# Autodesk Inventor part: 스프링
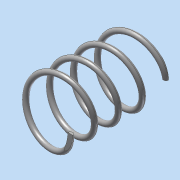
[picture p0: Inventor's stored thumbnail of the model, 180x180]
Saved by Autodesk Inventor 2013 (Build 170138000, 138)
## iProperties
Created: 2014-11
Part Number: 스프링
Material: 강철, 연강
Document SubType Name: Modeling
Designer: Administrator
Density: 7.86 g/cm^3
Mass: 2.84315 g
Surface Area: 9.78737 cm^2
Volume: 0.361724 cm^3
Author: Administrator
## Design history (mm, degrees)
sketch "스케치1"
  geometry: L1 (0, 0)-(0, 28); L2 (0, 0)-(8.25, 0); L3 (0, 28)-(8.25, 28); C1 r 0.75 at (8.25, 0)
  constraints: 6 end point, 2 parallel, 1 centre point, 1 coincident, 1 perpendicular, 1 vertical
  dimensions: "d0" = 28 distance of L1.start L1.end (derived); "d1" = 8.25 distance of L1.end L3.end; "d2" = 1.5 diameter of C1
feature "코일1" sketch "스케치1" pitch "d3" = 10; turns "d5" = 4; dims "d4" = 28 (= d0), "d6" = 0, angle "d7" = 90 deg, angle "d8" = 90 deg, "d9" = 0, "d10" = 0
sketch "스케치2"
  geometry: L1 (28, 12)-(0, 12); L2 (0, 12)-(0, -12); L3 (0, -12)-(28, -12); L4 (28, -12)-(28, 12); 2 further points
  constraints: 8 end point, 2 coincident, 2 parallel, 1 horizontal, 1 midpoint, 1 perpendicular
  dimensions: "d11" = 28 distance of L2.end L3.end (derived); "d13" = 24 distance between parallel lines of L3 L1
extrude "돌출1" sketch "스케치2" stored distance "d14" = 10; taper "d15" = 0 deg
node "솔리드1"
